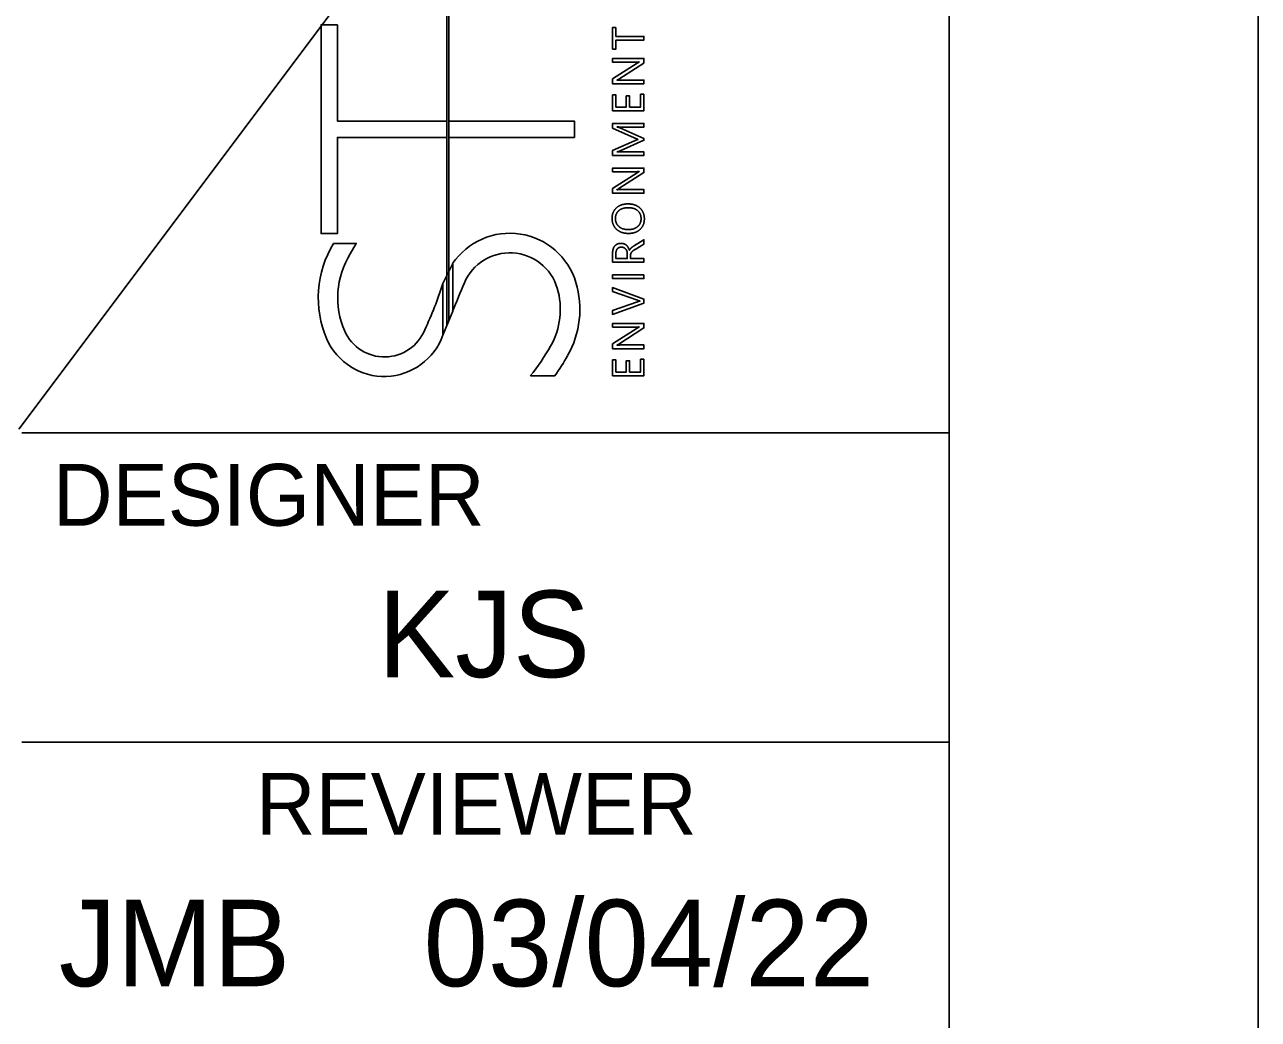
# Model space of a CAD drawing. Extents: x -4451 to 6119, y -1533 to 848.
# Drawn here: x 640.09 to 680, y 41.03 to 73.21 of the extents above; entities that cross this region are included whole.
import ezdxf

# ---------------------------------------------------------------- set-up
doc = ezdxf.new("R2010")
doc.units = 0
for name, color, linetype in [('SH_Border', 7, 'Continuous'), ('SH_Cut_Line', 7, 'Continuous'), ('SH_Data', 7, 'Continuous'), ('SH_Text', 7, 'Continuous')]:
    doc.layers.add(name, color=color, linetype=linetype)

msp = doc.modelspace()

# ---------------------------------------------------------------- linework, layer by layer
at = {"layer": 'SH_Border'}
for p, q in [((653.744, 76.108), (653.744, 63.483)), ((653.807, 76.108), (653.807, 63.637)), ((649.678, 66.451), (649.678, 73.207)), ((649.678, 73.207), (650.205, 73.207)), ((650.205, 73.207), (650.205, 70.093)), ((659.969, 72.001), (659.969, 72.004)), ((659.25, 71.418), (659.25, 71.414)), ((650.205, 70.093), (653.744, 70.093)), ((653.744, 70.093), (653.744, 69.565)), ((657.874, 70.093), (653.807, 70.093)), ((653.807, 70.093), (653.807, 69.565)), ((657.874, 69.565), (657.874, 70.093)), ((659.245, 69.905), (659.245, 69.902)), ((653.744, 69.565), (650.205, 69.565)), ((650.205, 69.565), (650.205, 66.451)), ((653.807, 69.565), (657.874, 69.565)), ((659.935, 69.495), (659.935, 69.5)), ((659.245, 69.094), (659.245, 69.091)), ((659.969, 68.457), (659.969, 68.46)), ((659.25, 67.873), (659.25, 67.869)), ((659.199, 66.938), (659.199, 66.938)), ((660.136, 66.929), (660.136, 66.929)), ((650.205, 66.451), (649.678, 66.451)), ((650.083, 66.132), (650.817, 66.132)), ((650.817, 66.132), (650.621, 65.8)), ((659.653, 65.912), (659.65, 65.912)), ((653.934, 65.479), (653.934, 63.945)), ((653.618, 64.834), (653.618, 63.17)), ((659.999, 64.267), (659.999, 64.269)), ((659.969, 63.429), (659.969, 63.432)), ((659.25, 62.845), (659.25, 62.841)), ((656.447, 61.847), (657.238, 61.847))]:
    msp.add_line(p, q, dxfattribs=at)
for points in [[(652.196, 77.272), (653.681, 76.905), (653.681, 76.108), (653.744, 76.108), (653.744, 63.483)], [(653.807, 63.637), (653.807, 76.108), (653.871, 76.108), (653.871, 76.858), (656.532, 76.198)], [(659.82, 71.997), (659.109, 71.997), (659.109, 72.116), (660.119, 72.116), (660.119, 71.97), (659.314, 71.45)], [(659.389, 71.419), (660.119, 71.419), (660.119, 71.301), (659.109, 71.301), (659.109, 71.455), (659.901, 71.961)], [(659.811, 69.548), (659.109, 69.865), (659.109, 70.013), (660.119, 70.013), (660.119, 69.895), (659.441, 69.895)], [(659.343, 69.872), (660.119, 69.526), (660.119, 69.469), (659.348, 69.124)], [(659.443, 69.096), (660.119, 69.096), (660.119, 68.982), (659.109, 68.982), (659.109, 69.139), (659.813, 69.449)], [(659.82, 68.453), (659.109, 68.453), (659.109, 68.571), (660.119, 68.571), (660.119, 68.426), (659.314, 67.906)], [(659.389, 67.875), (660.119, 67.875), (660.119, 67.756), (659.109, 67.756), (659.109, 67.91), (659.901, 68.416)], [(650.083, 66.132), (650.817, 66.132), (650.621, 65.8)], [(659.836, 65.941), (660.119, 66.11), (660.119, 66.251), (659.815, 66.062)], [(653.618, 63.17), (653.618, 64.834), (653.934, 65.479), (653.934, 63.945), (653.618, 63.17)], [(653.934, 65.479), (653.934, 63.945)], [(659.109, 65.828), (659.109, 65.527), (660.119, 65.527), (660.119, 65.645), (659.689, 65.645), (659.689, 65.742)], [(659.582, 65.806), (659.582, 65.645), (659.216, 65.645), (659.216, 65.807)], [(653.618, 64.834), (653.618, 63.17)], [(659.909, 64.293), (659.109, 64.578), (659.109, 64.706), (660.119, 64.331), (660.119, 64.201), (659.109, 63.834), (659.109, 63.966), (659.91, 64.246)], [(659.82, 63.425), (659.109, 63.425), (659.109, 63.543), (660.119, 63.543), (660.119, 63.398), (659.314, 62.878)], [(659.389, 62.847), (660.119, 62.847), (660.119, 62.728), (659.109, 62.728), (659.109, 62.882), (659.901, 63.388)], [(656.447, 61.847), (657.238, 61.847)]]:
    msp.add_lwpolyline(points, dxfattribs=at)
for points in [[(650.205, 73.207), (650.205, 70.093), (653.744, 70.093), (653.744, 69.565), (650.205, 69.565), (650.205, 66.451), (649.678, 66.451), (649.678, 73.207)], [(659.216, 73.124), (659.216, 72.833), (660.119, 72.833), (660.119, 72.714), (659.216, 72.714), (659.216, 72.423), (659.109, 72.423), (659.109, 73.124)], [(660.119, 70.96), (660.119, 70.425), (659.109, 70.425), (659.109, 70.938), (659.216, 70.938), (659.216, 70.543), (659.552, 70.543), (659.552, 70.908), (659.658, 70.908), (659.658, 70.543), (660.012, 70.543), (660.012, 70.96)], [(657.874, 69.565), (657.874, 70.093), (653.807, 70.093), (653.807, 69.565)], [(653.618, 64.834), (653.618, 63.17), (653.934, 63.945), (653.934, 65.479)], [(660.119, 65.115), (660.119, 64.996), (659.109, 64.996), (659.109, 65.115)], [(660.119, 62.388), (660.119, 61.852), (659.109, 61.852), (659.109, 62.365), (659.216, 62.365), (659.216, 61.971), (659.552, 61.971), (659.552, 62.336), (659.658, 62.336), (659.658, 61.971), (660.012, 61.971), (660.012, 62.388)]]:
    msp.add_lwpolyline(points, close=True, dxfattribs=at)
for centre, radius, start, end in [((655.784, 64.232), 2.231, 16.5745, 146.0238), ((655.784, 64.232), 2.231, 16.5745, 146.0238), ((652.927, 64.376), 3.342, 148.3019, 203.5607), ((652.927, 64.376), 3.342, 148.3019, 203.5607), ((652.927, 64.376), 2.71, 148.3019, 203.5607), ((652.927, 64.376), 2.71, 148.3019, 203.5607), ((655.784, 64.232), 1.599, 16.5745, 157.0643), ((655.784, 64.232), 1.599, 16.5745, 157.0643), ((641.562, 68.7), 12.66, 334.9549, 342.2202), ((641.562, 68.7), 12.66, 334.9549, 342.2202), ((803.96, 2.154), 162.253, 157.26686, 157.61476), ((803.96, 2.154), 162.253, 157.26686, 157.61476), ((655.009, 64.002), 2.408, 330.4358, 16.5745), ((655.009, 64.002), 2.408, 330.4358, 16.5745), ((655.009, 64.002), 3.04, 330.4358, 16.5745), ((655.009, 64.002), 3.04, 330.4358, 16.5745), ((803.96, 2.154), 162.253, 157.73234, 157.79136), ((803.96, 2.154), 162.253, 157.73234, 157.79136), ((651.715, 63.848), 2.02, 203.5866, 340.393), ((651.715, 63.848), 2.02, 203.5866, 340.393), ((651.727, 63.868), 1.407, 204.1173, 338.0239), ((651.727, 63.868), 1.407, 204.1173, 338.0239), ((650.787, 66.396), 7.261, 321.2094, 330.4358), ((650.787, 66.396), 7.261, 321.2094, 330.4358), ((650.787, 66.396), 7.893, 324.8109, 330.4358), ((650.787, 66.396), 7.893, 324.8109, 330.4358)]:
    msp.add_arc(centre, radius, start, end, dxfattribs=at)
for points in [[(659.969, 72.004), (659.925, 71.997), (659.82, 71.997)], [(659.901, 71.961), (659.951, 71.992), (659.969, 72.001)], [(659.314, 71.45), (659.283, 71.431), (659.25, 71.418)], [(659.25, 71.414), (659.283, 71.419), (659.389, 71.419)], [(659.441, 69.895), (659.361, 69.895), (659.245, 69.905)], [(659.245, 69.902), (659.313, 69.885), (659.343, 69.872)], [(659.935, 69.5), (659.851, 69.53), (659.811, 69.548)], [(659.813, 69.449), (659.894, 69.485), (659.935, 69.495)], [(659.348, 69.124), (659.314, 69.109), (659.245, 69.094)], [(659.245, 69.091), (659.305, 69.096), (659.443, 69.096)], [(659.969, 68.46), (659.925, 68.453), (659.82, 68.453)], [(659.901, 68.416), (659.951, 68.448), (659.969, 68.457)], [(659.314, 67.906), (659.283, 67.886), (659.25, 67.873)], [(659.25, 67.869), (659.283, 67.875), (659.389, 67.875)], [(659.233, 67.284), (659.092, 67.156), (659.092, 66.946)], [(659.199, 66.938), (659.199, 67.101), (659.308, 67.194)], [(659.601, 67.412), (659.374, 67.412), (659.233, 67.284)], [(659.308, 67.194), (659.417, 67.288), (659.617, 67.288)], [(659.992, 67.28), (659.849, 67.412), (659.601, 67.412)], [(659.617, 67.288), (659.813, 67.288), (659.921, 67.192)], [(659.921, 67.192), (660.03, 67.096), (660.03, 66.929)], [(660.136, 66.929), (660.136, 67.149), (659.992, 67.28)], [(659.092, 66.946), (659.092, 66.719), (659.237, 66.588)], [(659.314, 66.679), (659.199, 66.779), (659.199, 66.938)], [(659.615, 66.58), (659.428, 66.58), (659.314, 66.679)], [(659.916, 66.677), (659.802, 66.58), (659.615, 66.58)], [(660.03, 66.929), (660.03, 66.774), (659.916, 66.677)], [(659.994, 66.585), (660.136, 66.714), (660.136, 66.929)], [(659.237, 66.588), (659.382, 66.456), (659.626, 66.456)], [(659.626, 66.456), (659.853, 66.456), (659.994, 66.585)], [(659.125, 65.951), (659.109, 65.895), (659.109, 65.828)], [(659.175, 66.048), (659.142, 66.007), (659.125, 65.951)], [(659.26, 66.113), (659.209, 66.089), (659.175, 66.048)], [(659.216, 65.807), (659.216, 65.907), (659.261, 65.959)], [(659.378, 66.136), (659.31, 66.136), (659.26, 66.113)], [(659.261, 65.959), (659.307, 66.012), (659.388, 66.012)], [(659.475, 66.12), (659.431, 66.136), (659.378, 66.136)], [(659.388, 66.012), (659.433, 66.012), (659.469, 65.996)], [(659.469, 65.996), (659.505, 65.981), (659.53, 65.953)], [(659.553, 66.075), (659.519, 66.104), (659.475, 66.12)], [(659.53, 65.953), (659.555, 65.926), (659.569, 65.888)], [(659.612, 66.004), (659.588, 66.046), (659.553, 66.075)], [(659.569, 65.888), (659.582, 65.85), (659.582, 65.806)], [(659.65, 65.912), (659.636, 65.963), (659.612, 66.004)], [(659.678, 65.956), (659.664, 65.937), (659.653, 65.912)], [(659.713, 65.991), (659.693, 65.974), (659.678, 65.956)], [(659.757, 66.025), (659.732, 66.008), (659.713, 65.991)], [(659.723, 65.851), (659.741, 65.874), (659.769, 65.896)], [(659.815, 66.062), (659.782, 66.041), (659.757, 66.025)], [(659.769, 65.896), (659.796, 65.918), (659.836, 65.941)], [(659.689, 65.742), (659.689, 65.776), (659.697, 65.802)], [(659.697, 65.802), (659.706, 65.828), (659.723, 65.851)], [(659.999, 64.269), (659.957, 64.275), (659.909, 64.293)], [(659.91, 64.246), (659.949, 64.259), (659.999, 64.267)], [(659.969, 63.432), (659.925, 63.425), (659.82, 63.425)], [(659.901, 63.388), (659.951, 63.42), (659.969, 63.429)], [(659.314, 62.878), (659.283, 62.858), (659.25, 62.845)], [(659.25, 62.841), (659.283, 62.847), (659.389, 62.847)]]:
    msp.add_open_spline(points, degree=2, dxfattribs=at)
at = {"layer": 'SH_Cut_Line'}
msp.add_lwpolyline([(0, 0), (680, 0), (680, 440), (0, 440)], close=True, dxfattribs=at)
at = {"layer": 'SH_Data'}
for p, q in [((640, 60), (670, 60)), ((640, 50), (670, 50))]:
    msp.add_line(p, q, dxfattribs=at)
msp.add_lwpolyline([(30, 430), (670, 430), (670, 10), (30, 10)], close=True, dxfattribs=at)
at = {"layer": 'SH_Text'}
msp.add_line((639.898, 60.122), (669.898, 100.122), dxfattribs=at)

# ---------------------------------------------------------------- texts
at = {"layer": 'SH_Border'}
for s, height, p in [('DESIGNER', 2, (641, 57)), ('KJS', 2.8, (651.514, 52.1)), ('REVIEWER', 2, (647.566, 47)), ('JMB', 2.8, (641.192, 42.1)), ('03/04/22', 2.8, (652.993, 42.1))]:
    msp.add_text(s, height=height, dxfattribs=at).set_placement(p)

doc.saveas('drawing.dxf')
